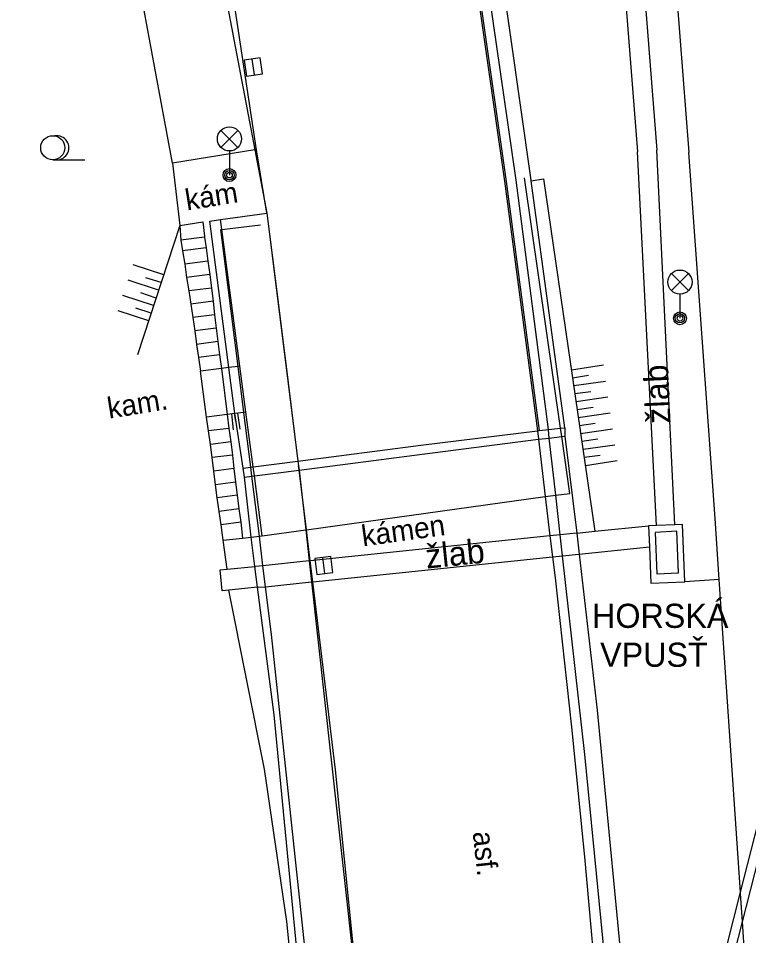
# Model space of a CAD drawing. Extents: x -599951 to -598963, y -1164095 to -1162939.
# Drawn here: x -599184.14 to -599161.45, y -1163615.69 to -1163587.19 of the extents above; entities that cross this region are included whole.
import ezdxf

# ---------------------------------------------------------------- set-up
doc = ezdxf.new("R2010")
doc.units = 0
for name, color, linetype in [('Level 10', 7, 'Continuous'), ('Level 11', 7, 'Continuous'), ('Level 14', 7, 'Continuous'), ('Level 15', 7, 'Continuous'), ('Level 27', 7, 'Continuous'), ('Level 33', 7, 'Continuous'), ('Level 36', 7, 'Continuous'), ('Level 40', 7, 'Continuous'), ('Level 41', 7, 'Continuous'), ('Level 9', 7, 'Continuous')]:
    doc.layers.add(name, color=color, linetype=linetype)

msp = doc.modelspace()

# ---------------------------------------------------------------- linework, layer by layer
at = {"layer": 'Level 10'}
for points in [[(-599178.77, -1163475.19), (-599175.21, -1163494.79), (-599171.85, -1163514.43), (-599170.18, -1163525.48), (-599168.97, -1163534.41), (-599167.98, -1163542.56), (-599166.71, -1163554.47), (-599165.92, -1163561.7), (-599164.81, -1163572.9), (-599164.14, -1163580.53), (-599163.3, -1163591.36)], [(-599176.74, -1163591.27), (-599177.47, -1163586.41), (-599178.32, -1163580.77)], [(-599176.42, -1163593.24), (-599176.74, -1163591.27)], [(-599162.36, -1163604.63), (-599162.49, -1163602.73), (-599163.3, -1163591.36)], [(-599168.01, -1163600.01), (-599167.98, -1163600.27)], [(-599167.98, -1163600.27), (-599167.77, -1163602.05)], [(-599175.41, -1163601.23), (-599175.43, -1163601.09)], [(-599175.19, -1163603.08), (-599175.41, -1163601.23)], [(-599167.77, -1163602.05), (-599167.62, -1163603.27)], [(-599175.07, -1163604.05), (-599175.19, -1163603.08)], [(-599167.62, -1163603.27), (-599167.54, -1163603.92)], [(-599167.54, -1163603.92), (-599167.46, -1163604.57), (-599166.95, -1163609.22), (-599166.55, -1163613.25), (-599166.08, -1163618.44)], [(-599174.99, -1163604.7), (-599175.07, -1163604.05)], [(-599173.42, -1163619.23), (-599173.45, -1163618.87), (-599174.28, -1163610.54), (-599174.99, -1163604.7)], [(-599161.7, -1163614.34), (-599162.36, -1163604.63)], [(-599161.7, -1163614.38), (-599161.7, -1163614.34)], [(-599161.64, -1163615.27), (-599161.7, -1163614.38)], [(-599161.5, -1163617.33), (-599161.64, -1163615.27)]]:
    msp.add_lwpolyline(points, dxfattribs=at)
at = {"layer": 'Level 11'}
for points in [[(-599168.2, -1163592.24), (-599168.21, -1163592.15), (-599169.76, -1163581.28), (-599171.51, -1163569.37), (-599172.98, -1163559.47), (-599174.44, -1163549.56), (-599175.91, -1163539.7), (-599177.37, -1163529.9), (-599178.86, -1163519.91), (-599180.33, -1163509.97), (-599181.82, -1163500.04), (-599183.4, -1163489.44)], [(-599184.14, -1163489.56), (-599182.57, -1163500.22), (-599181.1, -1163510.08), (-599179.65, -1163520.04), (-599178.17, -1163529.91), (-599176.71, -1163539.84), (-599175.24, -1163549.75), (-599173.77, -1163559.67), (-599172.34, -1163569.57), (-599170.59, -1163581.41), (-599169.03, -1163592.25), (-599168.01, -1163600.01)], [(-599166.28, -1163573.83), (-599164.9, -1163591.34)], [(-599165.68, -1163573.77), (-599164.3, -1163591.29)], [(-599176.79, -1163591.28), (-599179.35, -1163591.69)], [(-599176.74, -1163591.27), (-599176.79, -1163591.28)], [(-599164.31, -1163602.95), (-599164.9, -1163591.34)], [(-599163.74, -1163602.93), (-599164.3, -1163591.29)], [(-599179.35, -1163591.69), (-599179.12, -1163593.63)], [(-599161.7, -1163614.34), (-599157.3, -1163597.15), (-599155.83, -1163592)], [(-599167.29, -1163599.92), (-599168.41, -1163592.15)], [(-599168.2, -1163592.24), (-599167.82, -1163592.18), (-599166.22, -1163603.13)], [(-599167.16, -1163599.91), (-599168.2, -1163592.24)], [(-599178.19, -1163593.49), (-599177.86, -1163593.44)], [(-599177.6, -1163598.04), (-599178.19, -1163593.49)], [(-599177.86, -1163593.44), (-599176.42, -1163593.24)], [(-599177.82, -1163593.75), (-599177.86, -1163593.44)], [(-599176.42, -1163593.24), (-599176.17, -1163595.2), (-599175.85, -1163597.76), (-599175.45, -1163600.95), (-599175.43, -1163601.09)], [(-599179.12, -1163593.63), (-599178.41, -1163593.51), (-599178.35, -1163593.96), (-599178.35, -1163593.99)], [(-599179.12, -1163593.63), (-599179.09, -1163594.08)], [(-599177.26, -1163598), (-599177.82, -1163593.75)], [(-599178.35, -1163593.99), (-599179.09, -1163594.08)], [(-599178.35, -1163593.99), (-599178.3, -1163594.32)], [(-599179.09, -1163594.08), (-599179.04, -1163594.41)], [(-599178.3, -1163594.32), (-599179.04, -1163594.41)], [(-599178.3, -1163594.32), (-599178.25, -1163594.73)], [(-599179.04, -1163594.41), (-599178.97, -1163594.83)], [(-599178.25, -1163594.73), (-599178.97, -1163594.83)], [(-599178.97, -1163594.83), (-599178.91, -1163595.24)], [(-599178.25, -1163594.73), (-599178.19, -1163595.15)], [(-599178.19, -1163595.15), (-599178.91, -1163595.24)], [(-599178.19, -1163595.15), (-599178.14, -1163595.57)], [(-599178.91, -1163595.24), (-599178.84, -1163595.66)], [(-599178.14, -1163595.57), (-599178.84, -1163595.66)], [(-599178.84, -1163595.66), (-599178.78, -1163596.07)], [(-599178.14, -1163595.57), (-599178.09, -1163595.98)], [(-599178.09, -1163595.98), (-599178.78, -1163596.07)], [(-599178.09, -1163595.98), (-599178.04, -1163596.4)], [(-599178.78, -1163596.07), (-599178.72, -1163596.49)], [(-599178.04, -1163596.4), (-599178.72, -1163596.49)], [(-599178.72, -1163596.49), (-599178.66, -1163596.9)], [(-599178.04, -1163596.4), (-599177.99, -1163596.82)], [(-599177.99, -1163596.82), (-599178.66, -1163596.9)], [(-599178.66, -1163596.9), (-599178.6, -1163597.32)], [(-599177.99, -1163596.82), (-599177.94, -1163597.23)], [(-599177.94, -1163597.23), (-599178.6, -1163597.32)], [(-599178.6, -1163597.32), (-599178.54, -1163597.73)], [(-599177.94, -1163597.23), (-599177.89, -1163597.65)], [(-599177.89, -1163597.65), (-599178.54, -1163597.73)], [(-599178.54, -1163597.73), (-599178.48, -1163598.15)], [(-599177.89, -1163597.65), (-599177.83, -1163598.07)], [(-599177.6, -1163598.04), (-599177.83, -1163598.07)], [(-599177.31, -1163598.01), (-599177.6, -1163598.04)], [(-599177.41, -1163599.47), (-599177.6, -1163598.04)], [(-599177.26, -1163598), (-599177.31, -1163598.01)], [(-599177.07, -1163599.43), (-599177.26, -1163598)], [(-599177.83, -1163598.07), (-599178.48, -1163598.15)], [(-599178.29, -1163599.58), (-599178.48, -1163598.15)], [(-599177.83, -1163598.07), (-599177.65, -1163599.5)], [(-599177.41, -1163599.47), (-599177.65, -1163599.5)], [(-599177.13, -1163599.44), (-599177.41, -1163599.47)], [(-599177.15, -1163601.17), (-599177.41, -1163599.47)], [(-599177.07, -1163599.43), (-599177.13, -1163599.44)], [(-599176.84, -1163601.13), (-599177.07, -1163599.43)], [(-599177.65, -1163599.5), (-599178.29, -1163599.58)], [(-599178.23, -1163600.01), (-599178.29, -1163599.58)], [(-599177.65, -1163599.5), (-599177.6, -1163599.93)], [(-599177.6, -1163599.93), (-599178.23, -1163600.01)], [(-599178.17, -1163600.43), (-599178.23, -1163600.01)], [(-599177.6, -1163599.93), (-599177.54, -1163600.35)], [(-599175.45, -1163600.95), (-599171.63, -1163600.45), (-599168.01, -1163600.01)], [(-599168.01, -1163600.01), (-599167.96, -1163600)], [(-599167.96, -1163600), (-599167.67, -1163599.97)], [(-599167.67, -1163599.97), (-599167.29, -1163599.92)], [(-599167.29, -1163599.92), (-599167.16, -1163599.91)], [(-599167.25, -1163600.18), (-599167.29, -1163599.92)], [(-599167.16, -1163599.91), (-599167.16, -1163600.17)], [(-599175.41, -1163601.23), (-599171.59, -1163600.73), (-599167.98, -1163600.27)], [(-599167.98, -1163600.27), (-599167.64, -1163600.23)], [(-599167.64, -1163600.23), (-599167.25, -1163600.18)], [(-599167.44, -1163602.01), (-599167, -1163601.95), (-599167.25, -1163600.18)], [(-599167.25, -1163600.18), (-599167.16, -1163600.17)], [(-599167.16, -1163600.17), (-599166.78, -1163603.19)], [(-599177.54, -1163600.35), (-599178.17, -1163600.43)], [(-599178.12, -1163600.84), (-599178.17, -1163600.43)], [(-599177.54, -1163600.35), (-599177.49, -1163600.76)], [(-599177.49, -1163600.76), (-599178.12, -1163600.84)], [(-599178.06, -1163601.26), (-599178.12, -1163600.84)], [(-599177.49, -1163600.76), (-599177.44, -1163601.18)], [(-599177.44, -1163601.18), (-599178.06, -1163601.26)], [(-599177.44, -1163601.18), (-599177.39, -1163601.6)], [(-599177.15, -1163601.17), (-599176.92, -1163601.14)], [(-599177.11, -1163601.45), (-599177.15, -1163601.17)], [(-599176.92, -1163601.14), (-599176.84, -1163601.13)], [(-599176.84, -1163601.13), (-599175.45, -1163600.95)], [(-599176.8, -1163601.41), (-599176.84, -1163601.13)], [(-599178.01, -1163601.68), (-599178.06, -1163601.26)], [(-599177.11, -1163601.45), (-599176.88, -1163601.42)], [(-599176.91, -1163603.31), (-599177.11, -1163601.45)], [(-599176.88, -1163601.42), (-599176.8, -1163601.41)], [(-599176.8, -1163601.41), (-599175.41, -1163601.23)], [(-599176.56, -1163603.27), (-599176.8, -1163601.41)], [(-599177.39, -1163601.6), (-599178.01, -1163601.68)], [(-599177.96, -1163602.09), (-599178.01, -1163601.68)], [(-599177.39, -1163601.6), (-599177.34, -1163602.01)], [(-599177.34, -1163602.01), (-599177.96, -1163602.09)], [(-599177.34, -1163602.01), (-599177.29, -1163602.43)], [(-599175.19, -1163603.08), (-599167.77, -1163602.05)], [(-599167.77, -1163602.05), (-599167.44, -1163602.01)], [(-599177.9, -1163602.51), (-599177.96, -1163602.09)], [(-599177.29, -1163602.43), (-599177.9, -1163602.51)], [(-599177.84, -1163602.93), (-599177.9, -1163602.51)], [(-599177.29, -1163602.43), (-599177.23, -1163602.85)], [(-599177.23, -1163602.85), (-599177.84, -1163602.93)], [(-599177.23, -1163602.85), (-599177.17, -1163603.34)], [(-599177.78, -1163603.4), (-599177.84, -1163602.93)], [(-599176.56, -1163603.27), (-599175.21, -1163603.08)], [(-599175.21, -1163603.08), (-599175.19, -1163603.08)], [(-599166.8, -1163603.19), (-599167.3, -1163603.24)], [(-599166.8, -1163603.19), (-599166.78, -1163603.19)], [(-599166.78, -1163603.19), (-599166.22, -1163603.13)], [(-599166.78, -1163603.19), (-599166.71, -1163603.84)], [(-599166.22, -1163603.13), (-599164.56, -1163602.96)], [(-599164.31, -1163602.95), (-599164.56, -1163602.96)], [(-599164.56, -1163602.96), (-599164.53, -1163603.61)], [(-599163.63, -1163604.42), (-599163.68, -1163603.13), (-599164.35, -1163603.17), (-599164.3, -1163604.45), (-599163.63, -1163604.42)], [(-599163.74, -1163602.93), (-599164.31, -1163602.95)], [(-599163.43, -1163604.7), (-599163.5, -1163602.92), (-599163.74, -1163602.93)], [(-599177.78, -1163603.4), (-599177.17, -1163603.34)], [(-599177.65, -1163604.31), (-599177.78, -1163603.4)], [(-599177.17, -1163603.34), (-599176.91, -1163603.31)], [(-599176.91, -1163603.31), (-599176.65, -1163603.28)], [(-599176.79, -1163604.22), (-599176.91, -1163603.31)], [(-599176.65, -1163603.28), (-599176.56, -1163603.27)], [(-599167.62, -1163603.27), (-599175.07, -1163604.05)], [(-599167.3, -1163603.24), (-599167.62, -1163603.27)], [(-599166.71, -1163603.84), (-599164.53, -1163603.61)], [(-599164.53, -1163603.61), (-599164.49, -1163604.74), (-599163.43, -1163604.7)], [(-599174.99, -1163604.7), (-599167.54, -1163603.92)], [(-599167.54, -1163603.92), (-599167.23, -1163603.89)], [(-599167.23, -1163603.89), (-599166.72, -1163603.84)], [(-599166.72, -1163603.84), (-599166.71, -1163603.84)], [(-599166.71, -1163603.84), (-599166.15, -1163608.69), (-599165.23, -1163618.3), (-599165, -1163620.49)], [(-599177.87, -1163604.33), (-599177.65, -1163604.31)], [(-599177.81, -1163604.98), (-599177.87, -1163604.33)], [(-599177.65, -1163604.31), (-599176.79, -1163604.22)], [(-599176.79, -1163604.22), (-599176.77, -1163604.22)], [(-599176.71, -1163604.87), (-599176.79, -1163604.22)], [(-599176.54, -1163604.2), (-599176.77, -1163604.22)], [(-599175.1, -1163604.05), (-599176.54, -1163604.2)], [(-599175.07, -1163604.05), (-599175.1, -1163604.05)], [(-599176.71, -1163604.87), (-599177.6, -1163604.96)], [(-599176.69, -1163604.87), (-599176.71, -1163604.87)], [(-599175.11, -1163677.86), (-599174.84, -1163674.53), (-599173.95, -1163656.98), (-599173.87, -1163643.39), (-599174.3, -1163631.07), (-599175.13, -1163619.77), (-599176.19, -1163608.83), (-599176.71, -1163604.87)], [(-599176.69, -1163604.87), (-599176.46, -1163604.85)], [(-599176.46, -1163604.85), (-599175.03, -1163604.7)], [(-599175.03, -1163604.7), (-599174.99, -1163604.7)], [(-599162.36, -1163604.63), (-599163.43, -1163604.7)], [(-599177.6, -1163604.96), (-599177.81, -1163604.98)], [(-599176.14, -1163685.58), (-599175.61, -1163676.43), (-599174.99, -1163664.15), (-599174.55, -1163652.9), (-599174.53, -1163649.56), (-599174.7, -1163638.37), (-599174.9, -1163629.3), (-599175.26, -1163620.59), (-599175.8, -1163615.25), (-599176.49, -1163610.52), (-599177.6, -1163604.96)], [(-599163.35, -1163620.85), (-599161.7, -1163614.34)]]:
    msp.add_lwpolyline(points, dxfattribs=at)
at = {"layer": 'Level 14'}
for points in [[(-599184.09, -1163489.55), (-599182.5, -1163500.22), (-599181.03, -1163510.1), (-599179.57, -1163520.05), (-599178.12, -1163529.89), (-599176.66, -1163539.81), (-599175.19, -1163549.66), (-599173.72, -1163559.64), (-599172.28, -1163569.52), (-599170.53, -1163581.39), (-599168.98, -1163592.26), (-599167.96, -1163600)], [(-599179.35, -1163591.69), (-599180.23, -1163586.95), (-599180.87, -1163581.04)], [(-599179.12, -1163593.63), (-599180.44, -1163597.65)]]:
    msp.add_lwpolyline(points, dxfattribs=at)
at = {"layer": 'Level 15'}
for points in [[(-599179.62, -1163595.16), (-599180.57, -1163594.85)], [(-599179.78, -1163595.64), (-599180.73, -1163595.33)], [(-599179.7, -1163595.4), (-599180.18, -1163595.25)], [(-599179.86, -1163595.88), (-599180.33, -1163595.72)], [(-599179.94, -1163596.11), (-599180.89, -1163595.8)], [(-599180.09, -1163596.59), (-599181.04, -1163596.28)], [(-599180.01, -1163596.35), (-599180.49, -1163596.2)], [(-599166.95, -1163598.11), (-599165.96, -1163597.96)], [(-599166.92, -1163598.36), (-599166.42, -1163598.28)], [(-599166.88, -1163598.6), (-599165.89, -1163598.46)], [(-599166.85, -1163598.85), (-599166.35, -1163598.78)], [(-599166.81, -1163599.1), (-599165.82, -1163598.95)], [(-599177.52, -1163599.48), (-599177.46, -1163599.98)], [(-599177.43, -1163599.47), (-599177.39, -1163599.72)], [(-599177.33, -1163599.46), (-599177.26, -1163599.96)], [(-599166.77, -1163599.34), (-599166.28, -1163599.27)], [(-599166.74, -1163599.59), (-599165.75, -1163599.45)], [(-599166.7, -1163599.84), (-599166.21, -1163599.77)], [(-599166.67, -1163600.09), (-599165.68, -1163599.94)], [(-599166.63, -1163600.33), (-599166.13, -1163600.26)], [(-599166.59, -1163600.58), (-599165.6, -1163600.44)], [(-599166.56, -1163600.83), (-599166.06, -1163600.76)], [(-599166.52, -1163601.08), (-599165.53, -1163600.93)]]:
    msp.add_lwpolyline(points, dxfattribs=at)
at = {"layer": 'Level 27'}
for p, q in [((-599176.803, -1163588.947), (-599176.877, -1163588.453)), ((-599174.619, -1163604.438), (-599174.681, -1163603.942))]:
    msp.add_line(p, q, dxfattribs=at)
for points in [[(-599176.556, -1163588.91), (-599176.63, -1163588.416), (-599177.124, -1163588.49), (-599177.05, -1163588.984)], [(-599174.371, -1163604.407), (-599174.433, -1163603.911), (-599174.929, -1163603.973), (-599174.867, -1163604.469)]]:
    msp.add_lwpolyline(points, close=True, dxfattribs=at)
at = {"layer": 'Level 33'}
for p, q in [((-599177.845, -1163591.2), (-599177.315, -1163590.67)), ((-599177.845, -1163590.67), (-599177.315, -1163591.2)), ((-599177.58, -1163591.31), (-599177.58, -1163592.06)), ((-599163.845, -1163595.65), (-599163.315, -1163595.12)), ((-599163.845, -1163595.12), (-599163.315, -1163595.65)), ((-599163.58, -1163595.76), (-599163.58, -1163596.51))]:
    msp.add_line(p, q, dxfattribs=at)
for centre, radius in [((-599177.58, -1163590.935), 0.375), ((-599177.58, -1163592.06), 0.2), ((-599177.58, -1163592.06), 0.145), ((-599177.58, -1163592.06), 0.0876), ((-599163.58, -1163595.385), 0.375), ((-599163.58, -1163596.51), 0.2), ((-599163.58, -1163596.51), 0.145), ((-599163.58, -1163596.51), 0.0876)]:
    msp.add_circle(centre, radius, dxfattribs=at)
at = {"layer": 'Level 36'}
msp.add_line((-599183.07, -1163591.585), (-599182.07, -1163591.585), dxfattribs=at)
msp.add_circle((-599183.07, -1163591.21), 0.375, dxfattribs=at)
msp.add_arc((-599182.945, -1163591.21), 0.375, 260.4059, 99.5941, dxfattribs=at)
at = {"layer": 'Level 9'}
for points in [[(-599167.67, -1163599.97), (-599168.67, -1163592.22), (-599170.24, -1163581.32), (-599172, -1163569.43), (-599173.43, -1163559.56), (-599174.91, -1163549.61), (-599176.39, -1163539.76), (-599177.84, -1163529.83), (-599179.3, -1163519.89), (-599180.76, -1163510.01), (-599182.23, -1163500.12), (-599183.64, -1163490.35)], [(-599178.69, -1163580.89), (-599177.72, -1163586.37), (-599176.79, -1163591.28)], [(-599176.79, -1163591.28), (-599176.42, -1163593.24)], [(-599161.64, -1163615.27), (-599157.42, -1163598.74), (-599155.77, -1163592.84)], [(-599176.42, -1163593.24), (-599175.45, -1163600.95)], [(-599177.31, -1163598.01), (-599177.85, -1163593.75)], [(-599177.85, -1163593.75), (-599177.82, -1163593.75)], [(-599177.82, -1163593.75), (-599176.61, -1163593.61)], [(-599177.13, -1163599.44), (-599177.31, -1163598.01)], [(-599176.92, -1163601.14), (-599177.13, -1163599.44)], [(-599167.64, -1163600.23), (-599167.67, -1163599.97)], [(-599167.44, -1163602.01), (-599167.64, -1163600.23)], [(-599176.88, -1163601.42), (-599176.92, -1163601.14)], [(-599175.45, -1163600.95), (-599175.43, -1163601.09)], [(-599175.43, -1163601.09), (-599175.41, -1163601.23)], [(-599176.65, -1163603.28), (-599176.88, -1163601.42)], [(-599175.41, -1163601.23), (-599175.21, -1163603.08)], [(-599167.3, -1163603.24), (-599167.44, -1163602.01)], [(-599175.21, -1163603.08), (-599175.1, -1163604.05)], [(-599176.54, -1163604.2), (-599176.65, -1163603.28)], [(-599167.23, -1163603.89), (-599167.3, -1163603.24)], [(-599164.45, -1163631.6), (-599164.7, -1163629.05), (-599165.72, -1163618.41), (-599166.54, -1163610.06), (-599167.23, -1163603.89)], [(-599176.46, -1163604.85), (-599176.54, -1163604.2)], [(-599175.1, -1163604.05), (-599175.03, -1163604.7)], [(-599174.87, -1163677.83), (-599174.54, -1163674.48), (-599173.64, -1163657.14), (-599173.51, -1163647.14), (-599173.72, -1163636.91), (-599174.19, -1163627.77), (-599174.85, -1163619.65), (-599176.27, -1163606.34), (-599176.46, -1163604.85)], [(-599175.03, -1163604.7), (-599173.42, -1163619.23)], [(-599164.63, -1163628.24), (-599162.27, -1163617.74), (-599161.64, -1163615.27)]]:
    msp.add_lwpolyline(points, dxfattribs=at)

# ---------------------------------------------------------------- texts
at = {"layer": 'Level 40'}
for s, rotation, p in [('kám', 9.14, (-599178.9, -1163593.16)), ('kam.', 9.14, (-599181.32, -1163599.63)), ('kámen', 7.86, (-599173.43, -1163603.6)), ('asf.', 276.09, (-599170.02, -1163612.48))]:
    msp.add_text(s, height=0.65, rotation=rotation, dxfattribs=at).set_placement(p)
at = {"layer": 'Level 41'}
for rotation, p in [(92.66, (-599163.87, -1163599.77)), (5.89, (-599171.45, -1163604.29))]:
    msp.add_text('žlab', height=0.75, rotation=rotation, dxfattribs=at).set_placement(p)
for s, p in [('HORSKÁ', (-599166.31, -1163606.13)), ('VPUSŤ', (-599166.06, -1163607.34))]:
    msp.add_text(s, height=0.75, dxfattribs=at).set_placement(p)

doc.saveas('drawing.dxf')
